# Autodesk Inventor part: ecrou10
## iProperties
Shininess: 21.0
Length Units: 11269
Angle Units: 11279
Time Units: 11290
Mass Units: 11283
Length Display Precision: 3
Angle Display Precision: 2
Compacted: True
Created: 2001-12
Part Number: ecrou10
Material: Par défaut
Document SubType Name: Modélisation
Designer: pichon
Density: 0.0
Volumn: 0.0
Area: 0.0
PropertySet Name: Model Information
Control State: 0
Master: False
Checked Out: False
Author: pichon
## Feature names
1. Corps dérivé2 [Tagging]
